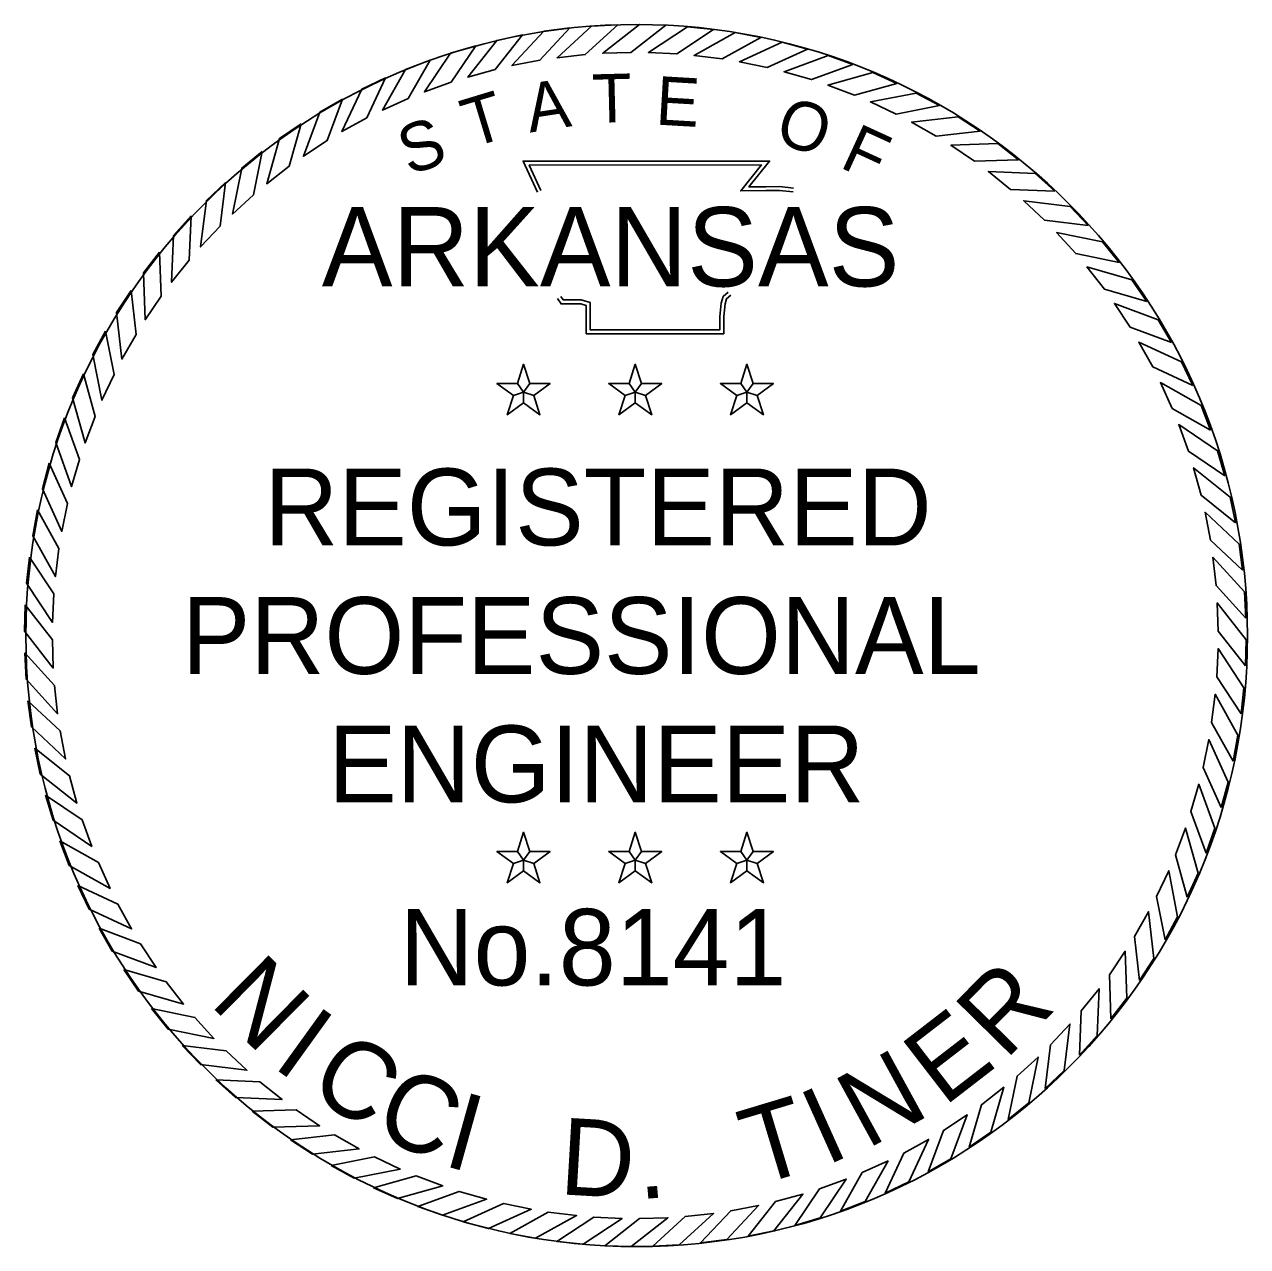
# Model space of a CAD drawing. Extents: x 759422 to 1467391, y 1662254 to 1691810.
# Drawn here: x 1467270.5 to 1467390.6, y 1691594.6 to 1691714.6 of the extents above; entities that cross this region are included whole.
import ezdxf

# ---------------------------------------------------------------- set-up
doc = ezdxf.new("R2010")
doc.units = 0
doc.layers.add('G-ANNO-STMP', color=7, linetype='Continuous')
doc.layers.add('G-No Plot-Stamp-1', color=7, linetype='Continuous')

msp = doc.modelspace()

# ---------------------------------------------------------------- linework, layer by layer
at = {"layer": 'G-ANNO-STMP'}
for points in [[(1467319.38, 1691713.52), (1467316.85, 1691712.99), (1467313.99, 1691709.39), (1467316.68, 1691710.13)], [(1467324.04, 1691714.21), (1467321.48, 1691713.88), (1467318.34, 1691710.52), (1467321.08, 1691711.04)], [(1467328.74, 1691714.53), (1467326.16, 1691714.4), (1467322.77, 1691711.29), (1467325.54, 1691711.6)], [(1467333.45, 1691714.48), (1467330.87, 1691714.55), (1467327.25, 1691711.72), (1467330.03, 1691711.81)], [(1467338.14, 1691714.06), (1467335.58, 1691714.33), (1467331.74, 1691711.8), (1467334.53, 1691711.67)], [(1467342.79, 1691713.27), (1467340.25, 1691713.75), (1467336.23, 1691711.52), (1467338.99, 1691711.17)], [(1467314.78, 1691712.47), (1467312.31, 1691711.74), (1467309.74, 1691707.93), (1467312.36, 1691708.88)], [(1467347.36, 1691712.12), (1467344.87, 1691712.8), (1467340.68, 1691710.89), (1467343.41, 1691710.33)], [(1467310.29, 1691711.06), (1467307.88, 1691710.14), (1467305.61, 1691706.14), (1467308.15, 1691707.29)], [(1467351.82, 1691710.62), (1467349.39, 1691711.49), (1467345.07, 1691709.91), (1467347.75, 1691709.14)], [(1467305.92, 1691709.31), (1467303.59, 1691708.2), (1467301.64, 1691704.03), (1467304.08, 1691705.38)], [(1467356.15, 1691708.77), (1467353.8, 1691709.83), (1467349.37, 1691708.6), (1467351.98, 1691707.61)], [(1467360.33, 1691706.59), (1467358.06, 1691707.82), (1467353.55, 1691706.95), (1467356.07, 1691705.76)], [(1467301.7, 1691707.21), (1467299.46, 1691705.93), (1467297.85, 1691701.62), (1467300.18, 1691703.15)], [(1467364.32, 1691704.08), (1467362.16, 1691705.49), (1467357.59, 1691704.97), (1467360.01, 1691703.59)], [(1467297.65, 1691704.79), (1467295.52, 1691703.34), (1467294.26, 1691698.92), (1467296.46, 1691700.63)], [(1467368.1, 1691701.27), (1467366.06, 1691702.85), (1467361.46, 1691702.69), (1467363.77, 1691701.12)], [(1467293.81, 1691702.07), (1467291.8, 1691700.45), (1467290.89, 1691695.94), (1467292.95, 1691697.82)], [(1467290.2, 1691699.05), (1467288.32, 1691697.27), (1467287.76, 1691692.71), (1467289.67, 1691694.74)], [(1467371.65, 1691698.17), (1467369.74, 1691699.91), (1467365.14, 1691700.11), (1467367.32, 1691698.36)], [(1467374.95, 1691694.81), (1467373.17, 1691696.68), (1467368.61, 1691697.24), (1467370.64, 1691695.34)], [(1467286.83, 1691695.75), (1467285.1, 1691693.84), (1467284.9, 1691689.24), (1467286.64, 1691691.42)], [(1467377.97, 1691691.19), (1467376.35, 1691693.2), (1467371.84, 1691694.12), (1467373.72, 1691692.06)], [(1467283.73, 1691692.2), (1467282.16, 1691690.16), (1467282.32, 1691685.56), (1467283.88, 1691687.87)], [(1467380.7, 1691687.35), (1467379.24, 1691689.48), (1467374.82, 1691690.75), (1467376.53, 1691688.55)], [(1467280.92, 1691688.42), (1467279.51, 1691686.26), (1467280.03, 1691681.69), (1467281.41, 1691684.11)], [(1467383.11, 1691683.31), (1467381.83, 1691685.55), (1467377.52, 1691687.16), (1467379.05, 1691684.83)], [(1467278.42, 1691684.43), (1467277.18, 1691682.16), (1467278.06, 1691677.65), (1467279.25, 1691680.17)], [(1467385.21, 1691679.09), (1467384.1, 1691681.42), (1467379.93, 1691683.36), (1467381.28, 1691680.92)], [(1467319.48, 1691678.45), (1467320.1, 1691679.29), (1467319.48, 1691681.19), (1467318.87, 1691679.29)], [(1467330.45, 1691678.45), (1467331.07, 1691679.29), (1467330.45, 1691681.19), (1467329.84, 1691679.29)], [(1467341.42, 1691678.45), (1467342.04, 1691679.29), (1467341.42, 1691681.19), (1467340.81, 1691679.29)], [(1467276.24, 1691680.25), (1467275.18, 1691677.9), (1467276.41, 1691673.47), (1467277.39, 1691676.07)], [(1467319.48, 1691678.45), (1467318.87, 1691679.29), (1467316.87, 1691679.29), (1467318.49, 1691678.12)], [(1467319.48, 1691678.45), (1467320.48, 1691678.12), (1467322.09, 1691679.29), (1467320.1, 1691679.29)], [(1467330.45, 1691678.45), (1467329.84, 1691679.29), (1467327.84, 1691679.29), (1467329.46, 1691678.12)], [(1467330.45, 1691678.45), (1467331.45, 1691678.12), (1467333.06, 1691679.29), (1467331.07, 1691679.29)], [(1467341.42, 1691678.45), (1467340.81, 1691679.29), (1467338.82, 1691679.29), (1467340.43, 1691678.12)], [(1467341.42, 1691678.45), (1467342.42, 1691678.12), (1467344.03, 1691679.29), (1467342.04, 1691679.29)], [(1467386.96, 1691674.72), (1467386.05, 1691677.13), (1467382.04, 1691679.39), (1467383.19, 1691676.85)], [(1467319.48, 1691678.45), (1467318.49, 1691678.12), (1467317.87, 1691676.23), (1467319.48, 1691677.4)], [(1467319.48, 1691678.45), (1467319.48, 1691677.4), (1467321.09, 1691676.23), (1467320.48, 1691678.12)], [(1467330.45, 1691678.45), (1467329.46, 1691678.12), (1467328.84, 1691676.23), (1467330.45, 1691677.4)], [(1467330.45, 1691678.45), (1467330.45, 1691677.4), (1467332.07, 1691676.23), (1467331.45, 1691678.12)], [(1467341.42, 1691678.45), (1467340.43, 1691678.12), (1467339.81, 1691676.23), (1467341.42, 1691677.4)], [(1467341.42, 1691678.45), (1467341.42, 1691677.4), (1467343.04, 1691676.23), (1467342.42, 1691678.12)], [(1467274.39, 1691675.92), (1467273.52, 1691673.49), (1467275.09, 1691669.17), (1467275.87, 1691671.85)], [(1467388.37, 1691670.22), (1467387.65, 1691672.7), (1467383.83, 1691675.27), (1467384.78, 1691672.65)], [(1467272.88, 1691671.46), (1467272.21, 1691668.96), (1467274.12, 1691664.78), (1467274.68, 1691667.51)], [(1467389.42, 1691665.63), (1467388.89, 1691668.15), (1467385.29, 1691671.02), (1467386.03, 1691668.33)], [(1467271.73, 1691666.89), (1467271.26, 1691664.35), (1467273.49, 1691660.33), (1467273.84, 1691663.09)], [(1467390.11, 1691660.97), (1467389.78, 1691663.53), (1467386.42, 1691666.66), (1467386.94, 1691663.93)], [(1467270.95, 1691662.24), (1467270.67, 1691659.68), (1467273.21, 1691655.84), (1467273.34, 1691658.63)], [(1467390.43, 1691656.27), (1467390.3, 1691658.84), (1467387.19, 1691662.23), (1467387.5, 1691659.46)], [(1467270.53, 1691657.55), (1467270.45, 1691654.97), (1467273.28, 1691651.35), (1467273.2, 1691654.13)], [(1467390.38, 1691651.56), (1467390.45, 1691654.14), (1467387.62, 1691657.76), (1467387.71, 1691654.97)], [(1467270.48, 1691652.84), (1467270.61, 1691650.26), (1467273.71, 1691646.87), (1467273.41, 1691649.64)], [(1467389.96, 1691646.86), (1467390.24, 1691649.43), (1467387.7, 1691653.26), (1467387.57, 1691650.48)], [(1467389.17, 1691642.22), (1467389.65, 1691644.75), (1467387.42, 1691648.78), (1467387.07, 1691646.01)], [(1467270.8, 1691648.14), (1467271.13, 1691645.58), (1467274.49, 1691642.44), (1467273.97, 1691645.18)], [(1467388.02, 1691637.65), (1467388.7, 1691640.14), (1467386.79, 1691644.33), (1467386.23, 1691641.6)], [(1467271.48, 1691643.48), (1467272.01, 1691640.95), (1467275.61, 1691638.09), (1467274.88, 1691640.78)], [(1467386.52, 1691633.18), (1467387.39, 1691635.62), (1467385.81, 1691639.94), (1467385.04, 1691637.26)], [(1467272.53, 1691638.88), (1467273.26, 1691636.41), (1467277.07, 1691633.84), (1467276.13, 1691636.46)], [(1467384.67, 1691628.85), (1467385.73, 1691631.21), (1467384.5, 1691635.64), (1467383.51, 1691633.03)], [(1467273.94, 1691634.39), (1467274.86, 1691631.98), (1467278.86, 1691629.71), (1467277.72, 1691632.25)], [(1467319.48, 1691632.5), (1467320.1, 1691633.35), (1467319.48, 1691635.24), (1467318.87, 1691633.35)], [(1467330.45, 1691632.5), (1467331.07, 1691633.35), (1467330.45, 1691635.24), (1467329.84, 1691633.35)], [(1467341.42, 1691632.5), (1467342.04, 1691633.35), (1467341.42, 1691635.24), (1467340.81, 1691633.35)], [(1467319.48, 1691632.5), (1467318.87, 1691633.35), (1467316.87, 1691633.35), (1467318.49, 1691632.18)], [(1467319.48, 1691632.5), (1467320.48, 1691632.18), (1467322.09, 1691633.35), (1467320.1, 1691633.35)], [(1467330.45, 1691632.5), (1467329.84, 1691633.35), (1467327.84, 1691633.35), (1467329.46, 1691632.18)], [(1467330.45, 1691632.5), (1467331.45, 1691632.18), (1467333.06, 1691633.35), (1467331.07, 1691633.35)], [(1467341.42, 1691632.5), (1467340.81, 1691633.35), (1467338.82, 1691633.35), (1467340.43, 1691632.18)], [(1467341.42, 1691632.5), (1467342.42, 1691632.18), (1467344.03, 1691633.35), (1467342.04, 1691633.35)], [(1467319.48, 1691632.5), (1467318.49, 1691632.18), (1467317.87, 1691630.28), (1467319.48, 1691631.45)], [(1467319.48, 1691632.5), (1467319.48, 1691631.45), (1467321.09, 1691630.28), (1467320.48, 1691632.18)], [(1467330.45, 1691632.5), (1467329.46, 1691632.18), (1467328.84, 1691630.28), (1467330.45, 1691631.45)], [(1467330.45, 1691632.5), (1467330.45, 1691631.45), (1467332.07, 1691630.28), (1467331.45, 1691632.18)], [(1467341.42, 1691632.5), (1467340.43, 1691632.18), (1467339.81, 1691630.28), (1467341.42, 1691631.45)], [(1467341.42, 1691632.5), (1467341.42, 1691631.45), (1467343.04, 1691630.28), (1467342.42, 1691632.18)], [(1467382.49, 1691624.68), (1467383.72, 1691626.94), (1467382.85, 1691631.46), (1467381.66, 1691628.93)], [(1467275.7, 1691630.02), (1467276.8, 1691627.68), (1467280.97, 1691625.74), (1467279.63, 1691628.18)], [(1467379.98, 1691620.69), (1467381.39, 1691622.85), (1467380.87, 1691627.42), (1467379.49, 1691624.99)], [(1467277.79, 1691625.8), (1467279.08, 1691623.56), (1467283.38, 1691621.95), (1467281.85, 1691624.28)], [(1467377.17, 1691616.9), (1467378.75, 1691618.95), (1467378.59, 1691623.54), (1467377.02, 1691621.24)], [(1467280.21, 1691621.75), (1467281.67, 1691619.62), (1467286.09, 1691618.36), (1467284.38, 1691620.56)], [(1467374.08, 1691613.36), (1467375.81, 1691615.27), (1467376.01, 1691619.86), (1467374.26, 1691617.69)], [(1467282.94, 1691617.91), (1467284.56, 1691615.9), (1467289.06, 1691614.99), (1467287.19, 1691617.05)], [(1467370.71, 1691610.06), (1467372.58, 1691611.83), (1467373.14, 1691616.4), (1467371.24, 1691614.36)], [(1467285.96, 1691614.3), (1467287.73, 1691612.42), (1467292.3, 1691611.86), (1467290.26, 1691613.77)], [(1467367.09, 1691607.04), (1467369.1, 1691608.66), (1467370.02, 1691613.16), (1467367.96, 1691611.29)], [(1467289.26, 1691610.93), (1467291.17, 1691609.2), (1467295.76, 1691609), (1467293.59, 1691610.74)], [(1467363.25, 1691604.31), (1467365.38, 1691605.77), (1467366.65, 1691610.19), (1467364.45, 1691608.48)], [(1467292.81, 1691607.83), (1467294.85, 1691606.26), (1467299.44, 1691606.42), (1467297.14, 1691607.98)], [(1467359.21, 1691601.89), (1467361.45, 1691603.18), (1467363.06, 1691607.48), (1467360.73, 1691605.95)], [(1467296.59, 1691605.02), (1467298.75, 1691603.61), (1467303.32, 1691604.13), (1467300.9, 1691605.51)], [(1467354.99, 1691599.8), (1467357.32, 1691600.9), (1467359.26, 1691605.07), (1467356.82, 1691603.73)], [(1467300.58, 1691602.52), (1467302.84, 1691601.28), (1467307.36, 1691602.16), (1467304.83, 1691603.35)], [(1467350.62, 1691598.04), (1467353.03, 1691598.96), (1467355.29, 1691602.96), (1467352.75, 1691601.82)], [(1467304.75, 1691600.33), (1467307.11, 1691599.28), (1467311.54, 1691600.51), (1467308.93, 1691601.49)], [(1467346.12, 1691596.63), (1467348.6, 1691597.36), (1467351.17, 1691601.17), (1467348.55, 1691600.23)], [(1467309.09, 1691598.49), (1467311.52, 1691597.62), (1467315.84, 1691599.19), (1467313.16, 1691599.97)], [(1467341.53, 1691595.58), (1467344.05, 1691596.11), (1467346.92, 1691599.71), (1467344.23, 1691598.98)], [(1467313.55, 1691596.98), (1467316.04, 1691596.31), (1467320.23, 1691598.22), (1467317.5, 1691598.78)], [(1467336.87, 1691594.9), (1467339.43, 1691595.23), (1467342.56, 1691598.59), (1467339.83, 1691598.07)], [(1467318.12, 1691595.83), (1467320.66, 1691595.36), (1467324.68, 1691597.59), (1467321.91, 1691597.93)], [(1467322.76, 1691595.05), (1467325.33, 1691594.77), (1467329.16, 1691597.31), (1467326.38, 1691597.44)], [(1467327.46, 1691594.63), (1467330.04, 1691594.55), (1467333.66, 1691597.38), (1467330.87, 1691597.3)], [(1467332.17, 1691594.58), (1467334.75, 1691594.71), (1467338.14, 1691597.81), (1467335.36, 1691597.51)]]:
    msp.add_lwpolyline(points, close=True, dxfattribs=at)
for points in [[(1467320.84, 1691698.1), (1467319.44, 1691701.13), (1467343.64, 1691701.14), (1467341.62, 1691698.6), (1467343.27, 1691698.62), (1467344.64, 1691698.64), (1467346.01, 1691698.49)], [(1467321.19, 1691698.26), (1467320.04, 1691700.75), (1467342.85, 1691700.76), (1467340.82, 1691698.21), (1467343.27, 1691698.24), (1467344.62, 1691698.26), (1467345.97, 1691698.11)], [(1467339.59, 1691688.26), (1467339.08, 1691687.84), (1467338.9, 1691687.19), (1467338.76, 1691685.89), (1467338.76, 1691684.58), (1467326.02, 1691684.58), (1467326.02, 1691686.45), (1467326.02, 1691687.24), (1467325.14, 1691687.5), (1467323.37, 1691687.5), (1467323.14, 1691687.85)], [(1467339.83, 1691687.96), (1467339.42, 1691687.62), (1467339.28, 1691687.12), (1467339.14, 1691685.87), (1467339.14, 1691684.19), (1467325.63, 1691684.19), (1467325.63, 1691686.45), (1467325.63, 1691686.95), (1467325.09, 1691687.12), (1467323.16, 1691687.12), (1467322.82, 1691687.64)]]:
    msp.add_lwpolyline(points, dxfattribs=at)
at = {"layer": 'G-No Plot-Stamp-1'}
msp.add_circle((1467330.59, 1691654.55), 60, dxfattribs=at)

# ---------------------------------------------------------------- texts
at = {"layer": 'G-ANNO-STMP'}
for s, height, rotation, p in [('A', 4.77, 8.6788, (1467320.1, 1691703.93)), ('T', 4.77, 1.4789, (1467326.27, 1691704.88)), ('E', 4.77, 356.672, (1467332.38, 1691704.73)), ('T', 4.77, 16.9015, (1467314.31, 1691702.41)), ('O', 4.77, 341.2218, (1467343.97, 1691703.09)), ('S', 4.77, 19.7726, (1467308.24, 1691699.69)), ('F', 4.77, 335.3628, (1467350.4, 1691700.58)), ('N', 7.54, 315.2676, (1467288.54, 1691618.37)), ('R', 7.54, 45.478, (1467366.79, 1691612.77)), ('I', 7.54, 324.2141, (1467294.67, 1691612.29)), ('E', 7.54, 37.6498, (1467360.76, 1691608.21)), ('C', 7.54, 328.6873, (1467298.08, 1691609.63)), ('N', 7.54, 28.7033, (1467353.19, 1691604.06)), ('C', 7.54, 336.5155, (1467304.5, 1691605.63)), ('I', 7.54, 344.3437, (1467311.4, 1691602.56)), ('T', 7.54, 16.7747, (1467342.26, 1691600.45)), ('I', 7.54, 24.2301, (1467349.18, 1691602.44)), ('D', 7.54, 356.6451, (1467322.92, 1691599.69)), ('.', 7.54, 4.846, (1467330.82, 1691599.18))]:
    msp.add_text(s, height=height, rotation=rotation, dxfattribs=at).set_placement(p)
for s, height, p in [('ARKANSAS', 7.791, (1467299.66, 1691688.83)), ('REGISTERED', 7.543, (1467294, 1691663.4)), ('PROFESSIONAL', 7.543, (1467285.91, 1691650.78)), ('ENGINEER', 7.543, (1467300.28, 1691638.17)), ('No.8141', 7.513, (1467307.31, 1691620.19))]:
    msp.add_text(s, height=height, dxfattribs=at).set_placement(p)

doc.saveas('drawing.dxf')
